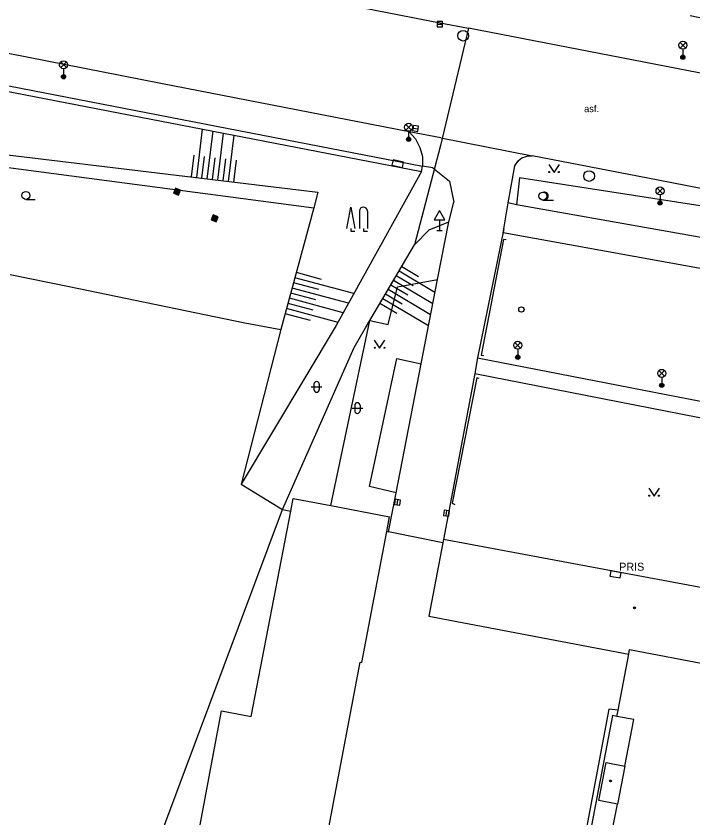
# Model space of a CAD drawing. Extents: x -599951 to -598963, y -1164095 to -1162939.
# Drawn here: x -599846.5 to -599783, y -1163123.5 to -1163048.3 of the extents above; entities that cross this region are included whole.
import ezdxf

# ---------------------------------------------------------------- set-up
doc = ezdxf.new("R2010")
doc.units = 0
for name, color, linetype in [('Level 1', 7, 'Continuous'), ('Level 10', 7, 'Continuous'), ('Level 11', 7, 'Continuous'), ('Level 14', 7, 'Continuous'), ('Level 15', 7, 'Continuous'), ('Level 24', 7, 'Continuous'), ('Level 25', 7, 'Continuous'), ('Level 27', 7, 'Continuous'), ('Level 31', 7, 'Continuous'), ('Level 33', 7, 'Continuous'), ('Level 34', 7, 'Continuous'), ('Level 36', 7, 'Continuous'), ('Level 39', 7, 'Continuous'), ('Level 40', 7, 'Continuous'), ('Level 41', 7, 'Continuous'), ('Level 5', 7, 'Continuous'), ('Level 52', 7, 'Continuous'), ('Level 7', 7, 'Continuous'), ('Level 8', 7, 'Continuous'), ('Level 9', 7, 'Continuous')]:
    doc.layers.add(name, color=color, linetype=linetype)

msp = doc.modelspace()

# ---------------------------------------------------------------- linework, layer by layer
at = {"layer": 'Level 1'}
msp.add_lwpolyline([(-599804.09, -1163049.47), (-599806.7, -1163060.46), (-599809.13, -1163069.78)], dxfattribs=at)
msp.add_lwpolyline([(-599804.09, -1163049.47), (-599806.7, -1163060.46), (-599809.13, -1163069.78)], dxfattribs=at)
at = {"layer": 'Level 10'}
for points in [[(-599860, -1163038.58), (-599806.72, -1163048.96)], [(-599832.94, -1163054.65), (-599865.1, -1163048.35)], [(-599806.72, -1163048.96), (-599804.09, -1163049.47)], [(-599806.72, -1163048.96), (-599804.09, -1163049.47)], [(-599742.38, -1163061.44), (-599756.85, -1163058.63), (-599804.09, -1163049.47)], [(-599809.63, -1163059.17), (-599832.94, -1163054.65)], [(-599809.63, -1163059.17), (-599809.04, -1163059.85)], [(-599809.04, -1163059.85), (-599808.63, -1163060.64)], [(-599808.63, -1163060.64), (-599808.4, -1163061.5)], [(-599808.4, -1163061.5), (-599808.38, -1163062.4)], [(-599799.72, -1163062.38), (-599799.4, -1163061.88), (-599799.08, -1163061.63)], [(-599799.08, -1163061.63), (-599798.678, -1163061.485), (-599798.58, -1163061.45), (-599798.11, -1163061.44)], [(-599762.43, -1163068.31), (-599775.73, -1163065.76), (-599786.29, -1163063.7), (-599798.11, -1163061.44)], [(-599807.41, -1163062.56), (-599808.38, -1163062.4)], [(-599807.41, -1163062.56), (-599805.86, -1163063.82)], [(-599807.41, -1163062.56), (-599805.86, -1163063.82)], [(-599800.36, -1163065.84), (-599799.72, -1163062.38)], [(-599805.86, -1163063.82), (-599805.45, -1163065.77)], [(-599805.93, -1163067.62), (-599805.45, -1163065.77)], [(-599800.77, -1163068.27), (-599800.36, -1163065.84)], [(-599808.53, -1163080.91), (-599806.99, -1163073.02), (-599805.93, -1163067.62)], [(-599800.77, -1163068.27), (-599803.22, -1163080.35)], [(-599803.22, -1163080.35), (-599803.47, -1163081.83)], [(-599810.86, -1163093.01), (-599808.53, -1163080.91)], [(-599803.47, -1163081.83), (-599806.41, -1163097.38)], [(-599811.59, -1163096.65), (-599810.86, -1163093.01)]]:
    msp.add_lwpolyline(points, dxfattribs=at)
at = {"layer": 'Level 11'}
for points in [[(-599752.45, -1163054.58), (-599771.39, -1163050.77), (-599783.29, -1163048.32)], [(-599852.59, -1163054.39), (-599808.47, -1163062.89)], [(-599852.51, -1163053.85), (-599808.38, -1163062.4)], [(-599806.66, -1163059.75), (-599809.63, -1163059.17)], [(-599806.66, -1163059.75), (-599798.11, -1163061.44)], [(-599806.66, -1163059.75), (-599798.11, -1163061.44)], [(-599808.47, -1163062.89), (-599808.38, -1163062.4)], [(-599799.29, -1163063.48), (-599799.58, -1163066.01)], [(-599776.09, -1163067.08), (-599799.29, -1163063.48)], [(-599799.58, -1163066.01), (-599800.36, -1163065.84)], [(-599763.17, -1163072.4), (-599773.46, -1163070.66), (-599799.58, -1163066.01)], [(-599800.83, -1163068.66), (-599800.77, -1163068.27)], [(-599763.84, -1163075.32), (-599800.83, -1163068.66)], [(-599847.06, -1163072.56), (-599841.69, -1163073.64)], [(-599816.97, -1163094.21), (-599813.32, -1163076.87), (-599811.61, -1163077.24), (-599810.75, -1163073.7), (-599806.99, -1163073.02)], [(-599841.69, -1163073.64), (-599825.06, -1163077.08)], [(-599825.06, -1163077.08), (-599821.66, -1163077.71)], [(-599810.86, -1163093.01), (-599813.35, -1163092.42), (-599810.8, -1163080.41), (-599808.53, -1163080.91)], [(-599803.22, -1163080.35), (-599765.76, -1163087.64), (-599756.68, -1163089.42), (-599741.9, -1163092.2), (-599742.25, -1163093.72)], [(-599803.47, -1163081.83), (-599766.12, -1163089.15)], [(-599811.73, -1163096.62), (-599811.59, -1163096.65)], [(-599790.04, -1163113.37), (-599790.91, -1163113.28), (-599793.31, -1163125.91), (-599792.5, -1163126.03)], [(-599790.16, -1163113.98), (-599790.56, -1163113.88), (-599792.78, -1163125.48), (-599792.41, -1163125.55)]]:
    msp.add_lwpolyline(points, dxfattribs=at)
at = {"layer": 'Level 14'}
for points in [[(-599862.4, -1163059.54), (-599818.2, -1163064.84)], [(-599808.47, -1163062.89), (-599816.48, -1163077.34)], [(-599818.2, -1163064.84), (-599818.58, -1163066.3)], [(-599807.76, -1163068.36), (-599805.93, -1163067.62)], [(-599809.13, -1163069.78), (-599807.76, -1163068.36)], [(-599814.81, -1163079.38), (-599813.73, -1163077.56), (-599813.32, -1163076.87), (-599809.13, -1163069.78)], [(-599814.81, -1163079.38), (-599813.73, -1163077.56), (-599813.32, -1163076.87), (-599809.13, -1163069.78)], [(-599816.48, -1163077.34), (-599825.39, -1163092.2)], [(-599821.51, -1163094.58), (-599814.81, -1163079.38)], [(-599821.51, -1163094.58), (-599814.81, -1163079.38)]]:
    msp.add_lwpolyline(points, dxfattribs=at)
at = {"layer": 'Level 15'}
for points in [[(-599829.05, -1163058.93), (-599829.59, -1163063.47)], [(-599828.06, -1163059.12), (-599828.6, -1163063.59)], [(-599827.08, -1163059.31), (-599827.61, -1163063.71)], [(-599826.09, -1163059.5), (-599826.61, -1163063.83)], [(-599829.84, -1163061.37), (-599830.09, -1163063.41)], [(-599828.85, -1163061.49), (-599829.1, -1163063.53)], [(-599827.86, -1163061.61), (-599828.1, -1163063.65)], [(-599826.87, -1163061.73), (-599827.11, -1163063.77)], [(-599825.87, -1163061.85), (-599826.12, -1163063.89)], [(-599817.86, -1163073.01), (-599820.22, -1163072.37)], [(-599807.23, -1163074.25), (-599810.59, -1163072.25)], [(-599808.76, -1163072.76), (-599810.34, -1163071.82)], [(-599814.82, -1163074.34), (-599820.35, -1163072.85)], [(-599807.43, -1163075.29), (-599811.1, -1163073.11)], [(-599809.27, -1163073.62), (-599810.85, -1163072.68)], [(-599815.32, -1163075.25), (-599820.61, -1163073.82)], [(-599818.12, -1163073.97), (-599820.48, -1163073.34)], [(-599807.63, -1163076.33), (-599811.61, -1163073.97)], [(-599809.78, -1163074.48), (-599811.36, -1163073.54)], [(-599818.38, -1163074.94), (-599820.74, -1163074.3)], [(-599810.29, -1163075.34), (-599811.87, -1163074.4)], [(-599818.64, -1163075.9), (-599821, -1163075.27)], [(-599815.82, -1163076.15), (-599820.87, -1163074.78)], [(-599810.8, -1163076.2), (-599812.38, -1163075.27)], [(-599807.84, -1163077.37), (-599812.12, -1163074.84)], [(-599818.9, -1163076.87), (-599821.26, -1163076.23)], [(-599816.31, -1163077.05), (-599821.13, -1163075.75)]]:
    msp.add_lwpolyline(points, dxfattribs=at)
at = {"layer": 'Level 24'}
for points in [[(-599811.253, -1163062.294), (-599810.277, -1163062.514), (-599810.167, -1163062.026), (-599811.143, -1163061.806)], [(-599790.827, -1163100.807), (-599789.842, -1163100.985), (-599789.753, -1163100.493), (-599790.738, -1163100.315)]]:
    msp.add_lwpolyline(points, close=True, dxfattribs=at)
at = {"layer": 'Level 25'}
for points in [[(-599831.734, -1163064.932), (-599831.268, -1163065.114), (-599831.086, -1163064.648), (-599831.552, -1163064.466)], [(-599831.669, -1163064.904), (-599831.296, -1163065.049), (-599831.151, -1163064.676), (-599831.524, -1163064.531)], [(-599831.604, -1163064.875), (-599831.325, -1163064.984), (-599831.216, -1163064.705), (-599831.495, -1163064.596)], [(-599831.539, -1163064.847), (-599831.353, -1163064.92), (-599831.28, -1163064.733), (-599831.467, -1163064.66)], [(-599831.475, -1163064.818), (-599831.381, -1163064.855), (-599831.345, -1163064.762), (-599831.438, -1163064.725)], [(-599828.204, -1163067.422), (-599827.738, -1163067.604), (-599827.556, -1163067.138), (-599828.022, -1163066.956)], [(-599828.139, -1163067.394), (-599827.766, -1163067.539), (-599827.621, -1163067.166), (-599827.994, -1163067.021)], [(-599828.074, -1163067.365), (-599827.795, -1163067.474), (-599827.686, -1163067.195), (-599827.965, -1163067.086)], [(-599828.01, -1163067.337), (-599827.823, -1163067.41), (-599827.75, -1163067.223), (-599827.937, -1163067.15)], [(-599827.945, -1163067.308), (-599827.852, -1163067.345), (-599827.815, -1163067.252), (-599827.908, -1163067.215)]]:
    msp.add_lwpolyline(points, close=True, dxfattribs=at)
at = {"layer": 'Level 27'}
for p, q in [((-599807, -1163049.11), (-599806.5, -1163049.11)), ((-599809.287, -1163058.829), (-599808.793, -1163058.911)), ((-599810.773, -1163094.148), (-599810.707, -1163093.652)), ((-599806.183, -1163095.158), (-599806.117, -1163094.662))]:
    msp.add_line(p, q, dxfattribs=at)
for points in [[(-599807, -1163049.36), (-599806.5, -1163049.36), (-599806.5, -1163048.86), (-599807, -1163048.86)], [(-599809.328, -1163059.075), (-599808.835, -1163059.158), (-599808.752, -1163058.665), (-599809.245, -1163058.582)], [(-599810.525, -1163094.181), (-599810.459, -1163093.685), (-599810.955, -1163093.619), (-599811.021, -1163094.115)], [(-599805.935, -1163095.191), (-599805.869, -1163094.695), (-599806.365, -1163094.629), (-599806.431, -1163095.124)]]:
    msp.add_lwpolyline(points, close=True, dxfattribs=at)
for centre in [(-599804.58, -1163050.18), (-599792.77, -1163063.33)]:
    msp.add_circle(centre, 0.5, dxfattribs=at)
at = {"layer": 'Level 31'}
msp.add_circle((-599799.12, -1163075.83), 0.25, dxfattribs=at)
at = {"layer": 'Level 33'}
for p, q in [((-599784.245, -1163051.33), (-599783.715, -1163050.8)), ((-599784.245, -1163050.8), (-599783.715, -1163051.33)), ((-599783.98, -1163051.44), (-599783.98, -1163052.19)), ((-599842.315, -1163053.17), (-599841.785, -1163052.64)), ((-599842.315, -1163052.64), (-599841.785, -1163053.17)), ((-599842.05, -1163053.28), (-599842.05, -1163054.03)), ((-599809.955, -1163059.02), (-599809.425, -1163058.49)), ((-599809.955, -1163058.49), (-599809.425, -1163059.02)), ((-599809.69, -1163059.13), (-599809.69, -1163059.88)), ((-599786.385, -1163064.99), (-599785.855, -1163064.46)), ((-599786.385, -1163064.46), (-599785.855, -1163064.99)), ((-599786.12, -1163065.1), (-599786.12, -1163065.85)), ((-599799.725, -1163079.45), (-599799.195, -1163078.92)), ((-599799.725, -1163078.92), (-599799.195, -1163079.45)), ((-599799.46, -1163079.56), (-599799.46, -1163080.31)), ((-599786.225, -1163082.08), (-599785.695, -1163081.55)), ((-599786.225, -1163081.55), (-599785.695, -1163082.08)), ((-599785.96, -1163082.19), (-599785.96, -1163082.94))]:
    msp.add_line(p, q, dxfattribs=at)
for centre, radius in [((-599783.98, -1163051.065), 0.375), ((-599783.98, -1163052.19), 0.2), ((-599783.98, -1163052.19), 0.145), ((-599783.98, -1163052.19), 0.0876), ((-599842.05, -1163052.905), 0.375), ((-599842.05, -1163054.03), 0.2), ((-599842.05, -1163054.03), 0.145), ((-599842.05, -1163054.03), 0.0876), ((-599809.69, -1163058.755), 0.375), ((-599809.69, -1163059.88), 0.2), ((-599809.69, -1163059.88), 0.145), ((-599809.69, -1163059.88), 0.0876), ((-599786.12, -1163064.725), 0.375), ((-599786.12, -1163065.85), 0.2), ((-599786.12, -1163065.85), 0.145), ((-599786.12, -1163065.85), 0.0876), ((-599799.46, -1163079.185), 0.375), ((-599799.46, -1163080.31), 0.2), ((-599799.46, -1163080.31), 0.145), ((-599799.46, -1163080.31), 0.0876), ((-599785.96, -1163081.815), 0.375), ((-599785.96, -1163082.94), 0.2), ((-599785.96, -1163082.94), 0.145), ((-599785.96, -1163082.94), 0.0876)]:
    msp.add_circle(centre, radius, dxfattribs=at)
at = {"layer": 'Level 34'}
for p, q in [((-599806.79, -1163067.422), (-599806.79, -1163068.44)), ((-599807.04, -1163068.44), (-599806.54, -1163068.44))]:
    msp.add_line(p, q, dxfattribs=at)
msp.add_lwpolyline([(-599807.29, -1163067.422), (-599806.29, -1163067.422), (-599806.79, -1163066.556)], close=True, dxfattribs=at)
at = {"layer": 'Level 36'}
for p, q in [((-599845.57, -1163065.525), (-599844.695, -1163065.525)), ((-599797.1, -1163065.575), (-599796.1, -1163065.575)), ((-599814.305, -1163066.615), (-599814.305, -1163068.24)), ((-599813.555, -1163066.615), (-599813.555, -1163068.24)), ((-599818.566, -1163082.836), (-599818.566, -1163083.336)), ((-599818.066, -1163082.836), (-599818.066, -1163083.336)), ((-599818.816, -1163083.086), (-599817.816, -1163083.086)), ((-599814.996, -1163085.066), (-599813.996, -1163085.066)), ((-599814.746, -1163084.816), (-599814.746, -1163085.316)), ((-599814.246, -1163084.816), (-599814.246, -1163085.316))]:
    msp.add_line(p, q, dxfattribs=at)
for points in [[(-599796.56, -1163062.25), (-599796.06, -1163063), (-599795.56, -1163062.25)], [(-599815.475, -1163068.24), (-599815.1, -1163066.24), (-599814.725, -1163068.24)], [(-599815.1, -1163068.24), (-599815.1, -1163068.49), (-599814.725, -1163068.49)], [(-599813.93, -1163068.24), (-599813.93, -1163068.49), (-599813.555, -1163068.49)], [(-599812.91, -1163078.72), (-599812.41, -1163079.47), (-599811.91, -1163078.72)], [(-599787.18, -1163092.58), (-599786.68, -1163093.33), (-599786.18, -1163092.58)]]:
    msp.add_lwpolyline(points, dxfattribs=at)
for centre, radius in [((-599796.51, -1163062.95), 0.05), ((-599795.611, -1163062.95), 0.05), ((-599845.57, -1163065.15), 0.375), ((-599797.1, -1163065.2), 0.375), ((-599812.86, -1163079.42), 0.05), ((-599811.961, -1163079.42), 0.05), ((-599787.13, -1163093.28), 0.05), ((-599786.231, -1163093.28), 0.05)]:
    msp.add_circle(centre, radius, dxfattribs=at)
for centre, radius, start, end in [((-599796.975, -1163065.2), 0.375, 260.40593, 99.59407), ((-599813.93, -1163066.615), 0.375, 0, 180), ((-599818.316, -1163082.836), 0.25, 0, 180), ((-599818.316, -1163083.336), 0.25, 180, 0), ((-599814.496, -1163084.816), 0.25, 0, 180), ((-599814.496, -1163085.316), 0.25, 180, 0)]:
    msp.add_arc(centre, radius, start, end, dxfattribs=at)
at = {"layer": 'Level 39'}
for centre, radius in [((-599788.52, -1163103.78), 0.09), ((-599788.52, -1163103.78), 0.0398), ((-599790.77, -1163120.01), 0.09), ((-599790.77, -1163120.01), 0.0398)]:
    msp.add_circle(centre, radius, dxfattribs=at)
at = {"layer": 'Level 5'}
for points in [[(-599806.47, -1163097.68), (-599807.8, -1163104.57)], [(-599806.41, -1163097.38), (-599806.47, -1163097.68)], [(-599768.92, -1163104.39), (-599806.41, -1163097.38)], [(-599807.8, -1163104.57), (-599789.04, -1163108.14)], [(-599789.04, -1163108.14), (-599788.98, -1163107.68)], [(-599788.98, -1163107.68), (-599781.45, -1163109.12)], [(-599790.04, -1163113.37), (-599789.04, -1163108.14)], [(-599790.16, -1163113.98), (-599790.04, -1163113.37)], [(-599788.59, -1163114.26), (-599790.16, -1163113.98)], [(-599789.43, -1163118.62), (-599788.59, -1163114.26)], [(-599791.85, -1163121.83), (-599791.17, -1163118.28)], [(-599791.17, -1163118.28), (-599789.43, -1163118.62)], [(-599789.43, -1163118.62), (-599790.12, -1163122.17)], [(-599790.12, -1163122.17), (-599791.85, -1163121.83)], [(-599790.82, -1163125.78), (-599790.12, -1163122.17)]]:
    msp.add_lwpolyline(points, dxfattribs=at)
at = {"layer": 'Level 52'}
for points in [[(-599820.74, -1163094.74), (-599820.51, -1163093.53), (-599816.97, -1163094.21), (-599811.47, -1163095.27)], [(-599828.43, -1163125.32), (-599829.41, -1163125.13), (-599827.25, -1163113.45), (-599824.47, -1163113.98), (-599820.74, -1163094.74)], [(-599811.73, -1163096.62), (-599811.47, -1163095.27)], [(-599818.11, -1163127.26), (-599817.73, -1163127.35), (-599814.25, -1163108.88), (-599814.08, -1163108.91), (-599811.73, -1163096.62)]]:
    msp.add_lwpolyline(points, dxfattribs=at)
at = {"layer": 'Level 7'}
for points in [[(-599862.41, -1163060.53), (-599818.58, -1163066.3)], [(-599818.58, -1163066.3), (-599821.66, -1163077.71)], [(-599821.66, -1163077.71), (-599825.39, -1163092.2)], [(-599825.39, -1163092.2), (-599821.51, -1163094.58)], [(-599825.39, -1163092.2), (-599821.51, -1163094.58)], [(-599840.71, -1163145.85), (-599821.51, -1163094.58)], [(-599840.71, -1163145.85), (-599821.51, -1163094.58)], [(-599821.51, -1163094.58), (-599820.74, -1163094.74)]]:
    msp.add_lwpolyline(points, dxfattribs=at)
at = {"layer": 'Level 8'}
msp.add_lwpolyline([(-599806.47, -1163097.68), (-599811.59, -1163096.65)], dxfattribs=at)
at = {"layer": 'Level 9'}
for points in [[(-599800.55, -1163069.32), (-599800.81, -1163069.26), (-599802.9, -1163080.1), (-599802.65, -1163080.15)], [(-599803.09, -1163082.29), (-599803.29, -1163082.22), (-599805.62, -1163093.99), (-599805.37, -1163094.11)]]:
    msp.add_lwpolyline(points, dxfattribs=at)

# ---------------------------------------------------------------- texts
at = {"layer": 'Level 40'}
msp.add_text('asf.', height=0.65, dxfattribs=at).set_placement((-599793.24, -1163057.34))
at = {"layer": 'Level 41'}
msp.add_text('PRIS', height=0.75, dxfattribs=at).set_placement((-599789.94, -1163100.31))

doc.saveas('drawing.dxf')
